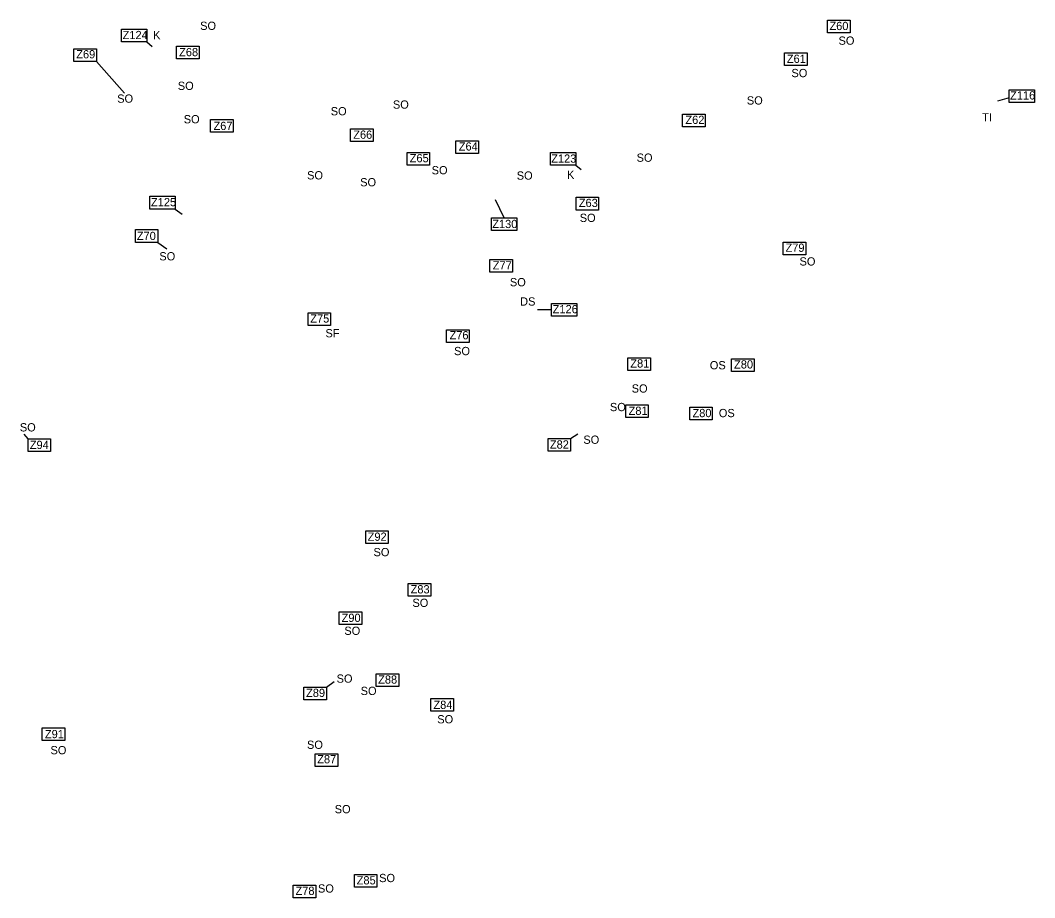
# Model space of a CAD drawing. Extents: x -443519 to -431242, y -1133468 to -1129615.
# Drawn here: x -441989 to -440759, y -1132600 to -1131536 of the extents above; entities that cross this region are included whole.
import ezdxf

# ---------------------------------------------------------------- set-up
doc = ezdxf.new("R2010")
doc.units = 0
for name, color, linetype in [('Vrstva 3', 7, 'Continuous'), ('Vrstva 4', 7, 'Continuous'), ('Vrstva 8', 7, 'Continuous')]:
    doc.layers.add(name, color=color, linetype=linetype)

msp = doc.modelspace()

# ---------------------------------------------------------------- linework, layer by layer
at = {"layer": 'Vrstva 3'}
for p, q in [((-441897, -1131586.3), (-441862.9, -1131625)), ((-440790.1, -1131630.6), (-440804.2, -1131634.7)), ((-441822.4, -1131805.7), (-441811.7, -1131813.5)), ((-441979.9, -1132043.8), (-441984.6, -1132038.4)), ((-441321.9, -1132043.4), (-441313.1, -1132037.9)), ((-441618.1, -1132344.9), (-441608.8, -1132338.2))]:
    msp.add_line(p, q, dxfattribs=at)
for points in [[(-441010.2, -1131536.4), (-440982.9, -1131536.4), (-440982.9, -1131551.8), (-441010.2, -1131551.8)], [(-441924.4, -1131570.9), (-441897, -1131570.9), (-441897, -1131586.3), (-441924.4, -1131586.3)], [(-441799.8, -1131567.7), (-441772.4, -1131567.7), (-441772.4, -1131583.1), (-441799.8, -1131583.1)], [(-441062.3, -1131575.9), (-441035, -1131575.9), (-441035, -1131591.3), (-441062.3, -1131591.3)], [(-440790.1, -1131620.9), (-440759.3, -1131620.9), (-440759.3, -1131636.2), (-440790.1, -1131636.2)], [(-441758.7, -1131656.9), (-441731.3, -1131656.9), (-441731.3, -1131672.3), (-441758.7, -1131672.3)], [(-441186, -1131650.3), (-441158.6, -1131650.3), (-441158.6, -1131665.7), (-441186, -1131665.7)], [(-441588.7, -1131668), (-441561.3, -1131668), (-441561.3, -1131683.4), (-441588.7, -1131683.4)], [(-441460.9, -1131682.5), (-441433.5, -1131682.5), (-441433.5, -1131697.9), (-441460.9, -1131697.9)], [(-441520.2, -1131696.6), (-441492.8, -1131696.6), (-441492.8, -1131712), (-441520.2, -1131712)], [(-441315.3, -1131751.1), (-441287.9, -1131751.1), (-441287.9, -1131766.5), (-441315.3, -1131766.5)], [(-441849.7, -1131790.3), (-441822.4, -1131790.3), (-441822.4, -1131805.7), (-441849.7, -1131805.7)], [(-441063.9, -1131805.5), (-441036.5, -1131805.5), (-441036.5, -1131820.9), (-441063.9, -1131820.9)], [(-441419.8, -1131826.6), (-441392.4, -1131826.6), (-441392.4, -1131842), (-441419.8, -1131842)], [(-441640.3, -1131891), (-441612.9, -1131891), (-441612.9, -1131906.4), (-441640.3, -1131906.4)], [(-441472.3, -1131911.6), (-441445, -1131911.6), (-441445, -1131927), (-441472.3, -1131927)], [(-441252.4, -1131945.8), (-441225, -1131945.8), (-441225, -1131961.2), (-441252.4, -1131961.2)], [(-441126.7, -1131946.9), (-441099.4, -1131946.9), (-441099.4, -1131962.3), (-441126.7, -1131962.3)], [(-441255, -1132002.7), (-441227.7, -1132002.7), (-441227.7, -1132018.1), (-441255, -1132018.1)], [(-441177.4, -1132005.6), (-441150, -1132005.6), (-441150, -1132021), (-441177.4, -1132021)], [(-441979.9, -1132043.8), (-441952.6, -1132043.8), (-441952.6, -1132059.2), (-441979.9, -1132059.2)], [(-441349.2, -1132043.4), (-441321.9, -1132043.4), (-441321.9, -1132058.8), (-441349.2, -1132058.8)], [(-441570.4, -1132155.6), (-441543.1, -1132155.6), (-441543.1, -1132171), (-441570.4, -1132171)], [(-441518.9, -1132219.3), (-441491.5, -1132219.3), (-441491.5, -1132234.7), (-441518.9, -1132234.7)], [(-441602.6, -1132253.6), (-441575.2, -1132253.6), (-441575.2, -1132269), (-441602.6, -1132269)], [(-441557.5, -1132329), (-441530.2, -1132329), (-441530.2, -1132344.4), (-441557.5, -1132344.4)], [(-441645.5, -1132344.9), (-441618.1, -1132344.9), (-441618.1, -1132360.3), (-441645.5, -1132360.3)], [(-441491.3, -1132358.9), (-441463.9, -1132358.9), (-441463.9, -1132374.3), (-441491.3, -1132374.3)], [(-441962.6, -1132394.5), (-441935.3, -1132394.5), (-441935.3, -1132409.9), (-441962.6, -1132409.9)], [(-441631.5, -1132425.8), (-441604.1, -1132425.8), (-441604.1, -1132441.2), (-441631.5, -1132441.2)], [(-441584.1, -1132572.3), (-441556.7, -1132572.3), (-441556.7, -1132587.7), (-441584.1, -1132587.7)], [(-441658.3, -1132585), (-441630.9, -1132585), (-441630.9, -1132600.4), (-441658.3, -1132600.4)]]:
    msp.add_lwpolyline(points, close=True, dxfattribs=at)
at = {"layer": 'Vrstva 8'}
for p, q in [((-441835.8, -1131562.7), (-441829.5, -1131568.4)), ((-441315.6, -1131712), (-441308.9, -1131717.3)), ((-441402.4, -1131775.9), (-441412.9, -1131754.3)), ((-441801.4, -1131765.3), (-441793.1, -1131771.6)), ((-441345, -1131887.4), (-441361.9, -1131887.4))]:
    msp.add_line(p, q, dxfattribs=at)
for points in [[(-441866.6, -1131547.3), (-441835.8, -1131547.3), (-441835.8, -1131562.7), (-441866.6, -1131562.7)], [(-441346.4, -1131696.6), (-441315.6, -1131696.6), (-441315.6, -1131712), (-441346.4, -1131712)], [(-441832.2, -1131749.9), (-441801.4, -1131749.9), (-441801.4, -1131765.3), (-441832.2, -1131765.3)], [(-441417.8, -1131775.9), (-441387.1, -1131775.9), (-441387.1, -1131791.3), (-441417.8, -1131791.3)], [(-441345, -1131879.7), (-441314.2, -1131879.7), (-441314.2, -1131895.1), (-441345, -1131895.1)]]:
    msp.add_lwpolyline(points, close=True, dxfattribs=at)

# ---------------------------------------------------------------- texts
at = {"layer": 'Vrstva 3'}
for s, p in [('Z60', (-441007.9, -1131548.3)), ('Z69', (-441921.5, -1131582.6)), ('Z68', (-441796.7, -1131580)), ('Z61', (-441059.6, -1131588.1)), ('Z116', (-440788.8, -1131632.5)), ('Z67', (-441755, -1131669.5)), ('Z62', (-441182.6, -1131662.1)), ('Z66', (-441585.5, -1131680.1)), ('Z64', (-441457.5, -1131694.4)), ('Z65', (-441517, -1131708.6)), ('Z63', (-441311.9, -1131762.9)), ('Z70', (-441848, -1131802.9)), ('Z79', (-441061.2, -1131817.2)), ('Z77', (-441416.3, -1131838.6)), ('Z75', (-441637.6, -1131903)), ('Z76', (-441468.7, -1131923.3)), ('Z81', (-441249.4, -1131957.5)), ('Z80', (-441123.6, -1131958.7)), ('Z81', (-441251.5, -1132014.9)), ('Z80', (-441174, -1132017.7)), ('Z94', (-441977.8, -1132056.3)), ('Z82', (-441347, -1132055.8)), ('Z92', (-441568, -1132167.6)), ('Z83', (-441515.9, -1132231.4)), ('Z90', (-441599.6, -1132266)), ('Z88', (-441555.3, -1132340.8)), ('Z89', (-441642.7, -1132357)), ('Z84', (-441488.2, -1132371.5)), ('Z91', (-441959.5, -1132407)), ('Z87', (-441629.2, -1132437.4)), ('Z85', (-441581.3, -1132584.3)), ('Z78', (-441655.5, -1132597))]:
    msp.add_text(s, height=10, dxfattribs=at).set_placement(p)
at = {"layer": 'Vrstva 4'}
for s, p in [('SO', (-441771.2, -1131548.1)), ('K', (-441828.3, -1131559.4)), ('SO', (-440996.9, -1131566.1)), ('SO', (-441054, -1131605.4)), ('SO', (-441798.3, -1131620.9)), ('SO', (-441871.8, -1131636.4)), ('SO', (-441537.4, -1131643.6)), ('SO', (-441108.1, -1131638.6)), ('SO', (-441612.8, -1131651.7)), ('SO', (-441791.1, -1131661.4)), ('TI', (-440822.6, -1131659.1)), ('SO', (-441241.8, -1131708)), ('SO', (-441641.5, -1131729.4)), ('SO', (-441490.4, -1131723.2)), ('SO', (-441387.2, -1131729.7)), ('K', (-441326.3, -1131728.7)), ('SO', (-441577.1, -1131737.8)), ('SO', (-441310.8, -1131781)), ('SO', (-441820.7, -1131827.6)), ('SO', (-441044.2, -1131833.8)), ('SO', (-441395.5, -1131859)), ('DS', (-441383.1, -1131882.4)), ('SF', (-441619.2, -1131920.9)), ('SO', (-441463.2, -1131942.5)), ('OS', (-441153, -1131959.7)), ('SO', (-441247.8, -1131987.9)), ('SO', (-441274.2, -1132010.4)), ('OS', (-441142.1, -1132017.7)), ('SO', (-441989.9, -1132035)), ('SO', (-441306.4, -1132050)), ('SO', (-441560.9, -1132186.3)), ('SO', (-441513.7, -1132247.8)), ('SO', (-441596.3, -1132281.7)), ('SO', (-441605.7, -1132339.7)), ('SO', (-441576.5, -1132354.6)), ('SO', (-441483.6, -1132389)), ('SO', (-441641.6, -1132419.9)), ('SO', (-441952.7, -1132426.5)), ('SO', (-441608, -1132498)), ('SO', (-441554.1, -1132581.5)), ('SO', (-441628.3, -1132594.2))]:
    msp.add_text(s, height=10, dxfattribs=at).set_placement(p)
at = {"layer": 'Vrstva 8'}
for s, p in [('Z124', (-441865.2, -1131559.3)), ('Z123', (-441345.4, -1131709.1)), ('Z125', (-441830.8, -1131761.9)), ('Z130', (-441416.9, -1131788.4)), ('Z126', (-441343.6, -1131891.7))]:
    msp.add_text(s, height=10, dxfattribs=at).set_placement(p)

doc.saveas('drawing.dxf')
